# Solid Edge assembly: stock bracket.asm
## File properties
Author: Deepak Maini
Template: normal.asm
Last saved by: MYPC
Revision: 4
Application: Solid Edge
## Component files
adjusting_nut_handle.par
adjusting_screw_guide.par
Stock_support_base.par
thrust_bearing.par
adjusting_screw_nut.par
support_adjusting_screw.par
support_roller_bracket.par
stock_support_roller.par
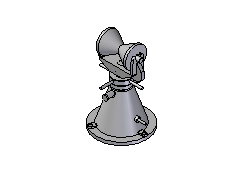
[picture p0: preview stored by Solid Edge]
